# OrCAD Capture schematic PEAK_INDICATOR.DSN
size A
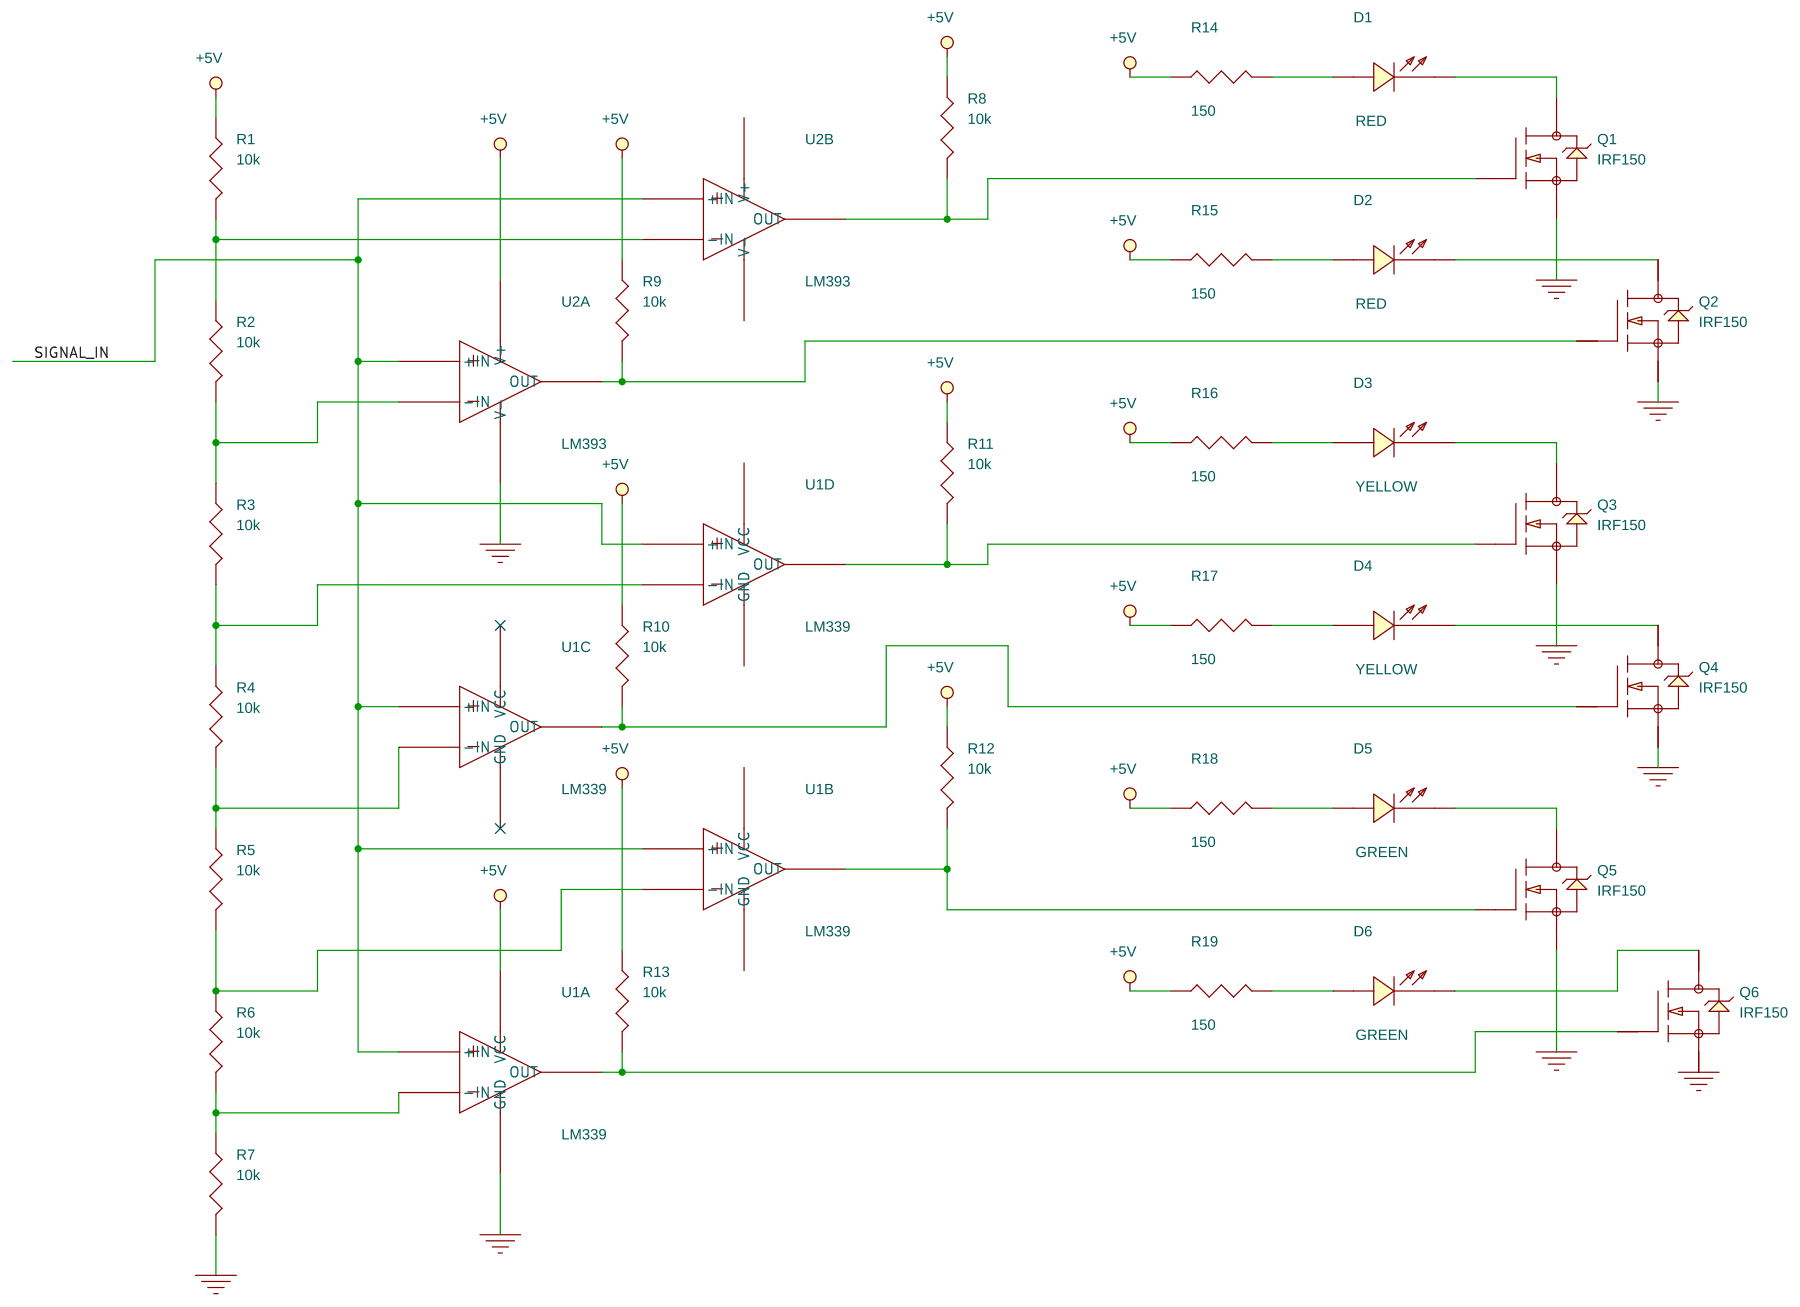
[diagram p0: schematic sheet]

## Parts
D1  RED  [LED_LNJ]
D2  RED  [LED_LNJ]
D3  YELLOW  [LED_LNJ]
D4  YELLOW  [LED_LNJ]
D5  GREEN  [LED_LNJ]
D6  GREEN  [LED_LNJ]
Q1  IRF150  [SOT-23_ONS]
Q2  IRF150  [SOT-23_ONS]
Q3  IRF150  [SOT-23_ONS]
Q4  IRF150  [SOT-23_ONS]
Q5  IRF150  [SOT-23_ONS]
Q6  IRF150  [SOT-23_ONS]
R1  10k  [0402-RES]
R2  10k  [0402-RES]
R3  10k  [0402-RES]
R4  10k  [0402-RES]
R5  10k  [0402-RES]
R6  10k  [0402-RES]
R7  10k  [0402-RES]
R8  10k  [0402-RES]
R9  10k  [0402-RES]
R10  10k  [0402-RES]
R11  10k  [0402-RES]
R12  10k  [0402-RES]
R13  10k  [0402-RES]
R14  150  [0402-RES]
R15  150  [0402-RES]
R16  150  [0402-RES]
R17  150  [0402-RES]
R18  150  [0402-RES]
R19  150  [0402-RES]
U1  LM339  (sections A,B,C,D)
U2  LM393  [SOIC8]  (sections A,B)

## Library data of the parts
D1-D6 = LED
Q1-Q6 = 2N7002
R1-R19 = RESISTOR
U1 = LM339_0
U2 = LM393_0

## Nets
+5V: R1.1 R8.1 R9.1 R10.1 R11.1 R12.1 R13.1 R14.1 R15.1 R16.1 R17.1 R18.1 R19.1 U1.3(VCC) U2.8(V+)
GND: Q1.2(SOURCE) Q2.2(SOURCE) Q3.2(SOURCE) Q4.2(SOURCE) Q5.2(SOURCE) Q6.2(SOURCE) R7.2 U1.12(GND) U2.4(V-)
SIGNAL_IN: U1.5(+IN) U1.7(+IN) U1.9(+IN) U1.11(+IN) U2.3(+IN) U2.5(+IN)
N00738: R1.2 R2.1 U2.6(-IN)
N00753: R2.2 R3.1 U2.2(-IN)
N00775: R3.2 R4.1 U1.10(-IN)
N00797: R4.2 R5.1 U1.8(-IN)
N00814: R5.2 R6.1 U1.4(-IN)
N00857: R6.2 R7.1 U1.6(-IN)
N01476: Q1.1(GATE) R8.2 U2.7(OUT)
N01707: Q2.1(GATE) R9.2 U2.1(OUT)
N01793: Q4.1(GATE) R10.2 U1.14(OUT)
N01864: Q3.1(GATE) R11.2 U1.13(OUT)
N01959: Q5.1(GATE) R12.2 U1.2(OUT)
N01992: Q6.1(GATE) R13.2 U1.1(OUT)
N02614: D1.2(ANODE) R14.2
N02750: D2.2(ANODE) R15.2
N02861: D3.2(ANODE) R16.2
N03008: D4.2(ANODE) R17.2
N03191: D5.2(ANODE) R18.2
N03243: D6.2(ANODE) R19.2
N03505: D1.1(CATHODE) Q1.3(DRAIN)
N03707: D2.1(CATHODE) Q2.3(DRAIN)
N03763: D3.1(CATHODE) Q3.3(DRAIN)
N03801: D4.1(CATHODE) Q4.3(DRAIN)
N03887: D5.1(CATHODE) Q5.3(DRAIN)
N03905: D6.1(CATHODE) Q6.3(DRAIN)
